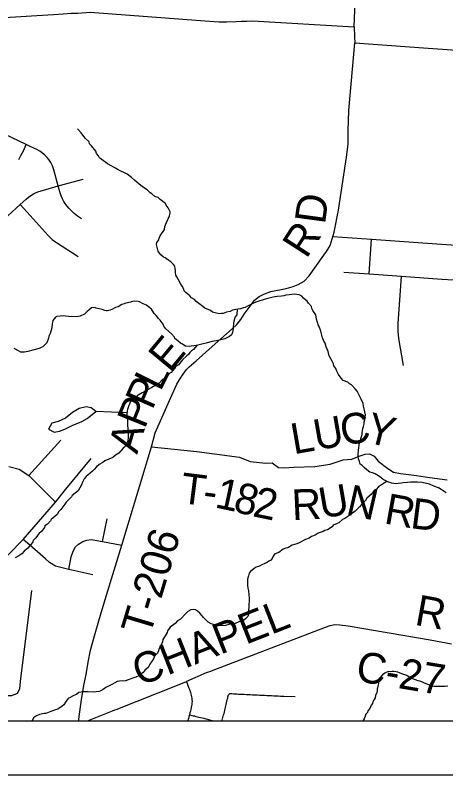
# Model space of a CAD drawing. Extents: x 0 to 34, y 0 to 22.
# Drawn here: x 3.374 to 4.173, y 14 to 15.409 of the extents above; entities that cross this region are included whole.
import ezdxf

# ---------------------------------------------------------------- set-up
doc = ezdxf.new("R2010")
doc.units = 0
for name, color, linetype in [('GM_X_Corporation', 7, 'Continuous'), ('GM_X_County_Road', 7, 'Continuous'), ('GM_X_County_Road_Text', 7, 'Continuous'), ('GM_X_Minor_Lake', 7, 'Continuous'), ('GM_X_Minor_River', 7, 'Continuous'), ('GM_X_Township_Road', 7, 'Continuous'), ('GM_X_Township_Road_Text', 7, 'Continuous'), ('SH_Data', 7, 'Continuous')]:
    doc.layers.add(name, color=color, linetype=linetype)

msp = doc.modelspace()

# ---------------------------------------------------------------- linework, layer by layer
at = {"layer": 'GM_X_Corporation'}
msp.add_lwpolyline([(2.9271, 14.1), (8.843, 14.1)], dxfattribs=at)
at = {"layer": 'GM_X_County_Road'}
msp.add_lwpolyline([(3.5081, 14.1), (3.5545, 14.1186), (3.559, 14.1205), (3.5612, 14.1214), (3.6782, 14.1678), (3.6919, 14.1734), (3.6922, 14.1735), (3.729, 14.1896), (3.7369, 14.1925), (3.7413, 14.1942), (3.9496, 14.2738), (3.9584, 14.277), (3.9672, 14.2787), (3.9763, 14.2784), (3.9918, 14.2761), (4.1437, 14.2504), (4.1833, 14.2432)], dxfattribs=at)
at = {"layer": 'GM_X_Minor_Lake'}
for points in [[(3.5235, 14.6739), (3.5152, 14.6809), (3.5057, 14.6826), (3.4928, 14.6794), (3.4801, 14.6724), (3.4674, 14.6616), (3.4539, 14.6557), (3.4417, 14.6525), (3.4358, 14.6412), (3.446, 14.6354), (3.4559, 14.6378), (3.4662, 14.6411), (3.4797, 14.6481)], [(3.4797, 14.6481), (3.4873, 14.6514), (3.4973, 14.6554), (3.5073, 14.6609), (3.5235, 14.6739)]]:
    msp.add_lwpolyline(points, dxfattribs=at)
at = {"layer": 'GM_X_Minor_River'}
for points in [[(3.6329, 15.0726), (3.6273, 15.078), (3.6243, 15.08), (3.6187, 15.0854), (3.6157, 15.0874), (3.6093, 15.0913), (3.604, 15.0959), (3.5999, 15.0994), (3.5954, 15.1029), (3.5898, 15.108), (3.5815, 15.1146), (3.5653, 15.1225), (3.56, 15.1252), (3.5454, 15.1338), (3.542, 15.1362), (3.5333, 15.142), (3.5303, 15.1448), (3.5285, 15.1482), (3.5251, 15.1528), (3.5237, 15.1567), (3.5155, 15.1667), (3.5121, 15.1709), (3.5111, 15.1744), (3.5043, 15.1802), (3.5013, 15.1841), (3.4961, 15.191), (3.4894, 15.1983)], [(3.9737, 14.7426), (3.97, 14.7499), (3.9686, 14.7537), (3.9652, 14.7587), (3.9645, 14.7625), (3.962, 14.7675), (3.9564, 14.7775), (3.9546, 14.7852), (3.9506, 14.794), (3.9492, 14.8005), (3.9466, 14.8047), (3.9441, 14.8108), (3.943, 14.8154), (3.9408, 14.823), (3.9376, 14.8315), (3.9361, 14.8349), (3.9346, 14.8391), (3.9328, 14.8452), (3.9315, 14.8533), (3.9263, 14.8613), (3.9244, 14.8652), (3.9237, 14.869), (3.9178, 14.8752), (3.9155, 14.879), (3.9088, 14.8845), (3.9058, 14.8883), (3.9005, 14.8903), (3.8964, 14.8911), (3.8918, 14.8916), (3.8869, 14.8913), (3.8823, 14.8902), (3.8758, 14.89), (3.8724, 14.8889), (3.8678, 14.8878), (3.8602, 14.8872), (3.8526, 14.8862), (3.84, 14.883), (3.8357, 14.8816), (3.8243, 14.8783), (3.8201, 14.8769), (3.8159, 14.8751), (3.8101, 14.8721), (3.8048, 14.8696), (3.8005, 14.867), (3.7975, 14.8663), (3.7917, 14.8645), (3.783, 14.8631), (3.7773, 14.8621), (3.773, 14.8598), (3.7662, 14.8581), (3.7631, 14.857), (3.7597, 14.8559), (3.7566, 14.8556), (3.7524, 14.8553), (3.7403, 14.8585), (3.7362, 14.8613), (3.726, 14.866), (3.7219, 14.8691), (3.7099, 14.8781), (3.7065, 14.8819), (3.7008, 14.8851), (3.6979, 14.8886), (3.6904, 14.8948), (3.6874, 14.8982), (3.6859, 14.9021), (3.6837, 14.9063), (3.6804, 14.9117), (3.6771, 14.9186), (3.6737, 14.924), (3.6719, 14.927), (3.6712, 14.932), (3.6713, 14.9354), (3.6706, 14.9388), (3.6699, 14.9434), (3.6677, 14.9469), (3.6624, 14.9515), (3.6591, 14.9543), (3.6549, 14.9574), (3.6519, 14.9593), (3.6489, 14.9605), (3.6444, 14.9648), (3.6414, 14.9675), (3.6392, 14.9713), (3.6381, 14.9767), (3.6364, 14.9839), (3.6368, 14.9877), (3.6403, 14.9926), (3.6411, 14.9956), (3.6431, 15.0002), (3.6509, 15.0118), (3.6517, 15.0171), (3.6545, 15.0247), (3.6601, 15.0368), (3.6613, 15.0417), (3.6613, 15.0447), (3.658, 15.0516), (3.6539, 15.0566), (3.6525, 15.0601), (3.6427, 15.0671), (3.6393, 15.071), (3.6329, 15.0726)], [(3.786, 14.8636), (3.7851, 14.8536), (3.782, 14.8498), (3.7796, 14.8419), (3.7791, 14.8388), (3.7786, 14.8289), (3.7778, 14.8236), (3.7769, 14.8206), (3.7753, 14.8165), (3.7715, 14.8131), (3.7627, 14.8087), (3.7577, 14.8076), (3.7474, 14.8052), (3.7386, 14.8042), (3.7283, 14.8009), (3.7226, 14.7995), (3.7104, 14.7967), (3.7005, 14.795), (3.6974, 14.7946), (3.6898, 14.7955), (3.6834, 14.7998), (3.6808, 14.801), (3.6756, 14.8053), (3.6703, 14.8092), (3.6692, 14.8119), (3.664, 14.8184), (3.6535, 14.8277), (3.6498, 14.8324), (3.6483, 14.8358), (3.6431, 14.8435), (3.6398, 14.8466), (3.6353, 14.8524), (3.6319, 14.8559), (3.6271, 14.8636), (3.6245, 14.8655), (3.6174, 14.8713), (3.6113, 14.8737), (3.6045, 14.8776), (3.6019, 14.8781), (3.5954, 14.8786), (3.5916, 14.8779), (3.5878, 14.8768), (3.579, 14.8751), (3.576, 14.874), (3.5718, 14.8725), (3.5648, 14.8685), (3.5599, 14.867), (3.5534, 14.863), (3.5499, 14.8619), (3.5453, 14.8608), (3.5427, 14.8609), (3.54, 14.8617), (3.5355, 14.8633), (3.5241, 14.8657), (3.5215, 14.8669), (3.5158, 14.8663), (3.5108, 14.8618), (3.5073, 14.8596), (3.5023, 14.8547), (3.4942, 14.8507), (3.4885, 14.8496), (3.4729, 14.8503), (3.4672, 14.8512), (3.4638, 14.8516), (3.4512, 14.8503), (3.4486, 14.8488), (3.4435, 14.8428), (3.4431, 14.839), (3.4427, 14.8364), (3.4418, 14.8292), (3.4389, 14.819), (3.4362, 14.8137), (3.4357, 14.8099), (3.4326, 14.8016), (3.4302, 14.7989), (3.4252, 14.7941), (3.4221, 14.7926), (3.4187, 14.7908), (3.4069, 14.7876), (3.3973, 14.7851), (3.3912, 14.7844), (3.3847, 14.7842), (3.3798, 14.7865), (3.3719, 14.7912)], [(3.7116, 14.797), (3.7046, 14.7888), (3.7011, 14.7866), (3.698, 14.7832), (3.6953, 14.7795), (3.6926, 14.7772), (3.6841, 14.7698), (3.6767, 14.7608), (3.6713, 14.7567), (3.6697, 14.7537), (3.6632, 14.7462), (3.6593, 14.7436), (3.6527, 14.7365), (3.647, 14.7331), (3.6408, 14.7264), (3.635, 14.7223), (3.6308, 14.7205), (3.6273, 14.7183), (3.6193, 14.7142), (3.6127, 14.7102), (3.6093, 14.7087), (3.6005, 14.7028), (3.5974, 14.6994), (3.5873, 14.6916), (3.5858, 14.6878), (3.5846, 14.6852), (3.5826, 14.678), (3.5817, 14.675), (3.5813, 14.6689), (3.5815, 14.6624), (3.5822, 14.6563), (3.5824, 14.6479), (3.5827, 14.6422), (3.583, 14.6384), (3.5833, 14.6293), (3.5836, 14.6259), (3.5831, 14.6194), (3.5815, 14.6164), (3.5772, 14.6085), (3.5745, 14.6063), (3.566, 14.5969), (3.5602, 14.5932), (3.5548, 14.5887), (3.5403, 14.5825), (3.5368, 14.5795), (3.5299, 14.5755), (3.5249, 14.5714), (3.5202, 14.5665), (3.5171, 14.5631), (3.509, 14.5557), (3.5059, 14.5535), (3.5021, 14.549), (3.4997, 14.5441), (3.4962, 14.5365), (3.4938, 14.5327), (3.491, 14.5267), (3.4795, 14.5182), (3.4783, 14.5155), (3.4729, 14.5099), (3.4683, 14.5058), (3.4663, 14.5024), (3.4589, 14.4923), (3.455, 14.4886), (3.4519, 14.4829), (3.4404, 14.4736), (3.4392, 14.471), (3.4341, 14.4653), (3.4291, 14.462), (3.4283, 14.459), (3.4225, 14.4515), (3.4186, 14.4481), (3.4124, 14.4395), (3.4074, 14.435), (3.4066, 14.4323), (3.4023, 14.426), (3.3996, 14.4233), (3.3976, 14.4203), (3.3903, 14.4148), (3.3861, 14.4099), (3.3807, 14.4062), (3.3738, 14.4025)], [(4.1734, 14.5231), (4.1696, 14.5254), (4.1644, 14.5293), (4.1595, 14.5324), (4.1508, 14.5356), (4.1425, 14.5392), (4.1292, 14.5421), (4.1201, 14.543), (4.1129, 14.5432), (4.1072, 14.5429), (4.1019, 14.5426), (4.0939, 14.5416), (4.0904, 14.5409), (4.0843, 14.5402), (4.0802, 14.5399), (4.0726, 14.5408), (4.0635, 14.544), (4.0601, 14.546), (4.0567, 14.5476), (4.05, 14.5534), (4.0417, 14.5581), (4.0368, 14.5605), (4.0319, 14.5617), (4.0266, 14.5656), (4.0214, 14.5702), (4.0176, 14.5737), (4.0142, 14.5765), (4.0128, 14.581), (4.0106, 14.5864), (4.0103, 14.5906), (4.0104, 14.5955), (4.0113, 14.6073), (4.0122, 14.6107), (4.0122, 14.6141), (4.015, 14.6198), (4.0154, 14.624), (4.0174, 14.6312), (4.0175, 14.635), (4.0191, 14.6422), (4.02, 14.646), (4.0212, 14.6509), (4.0216, 14.6547), (4.0229, 14.6592), (4.0238, 14.6676), (4.0213, 14.679), (4.0202, 14.684), (4.0196, 14.6886), (4.0159, 14.697), (4.0107, 14.7066), (4.0082, 14.712), (4.0048, 14.7158), (3.9981, 14.7232), (3.9939, 14.7251), (3.991, 14.7286), (3.9826, 14.7318), (3.9785, 14.7357), (3.9737, 14.7426)], [(3.5815, 14.6718), (3.5235, 14.6739)], [(4.0635, 14.544), (4.0554, 14.5392), (4.0477, 14.534), (4.0439, 14.5295), (4.0381, 14.5251), (4.0342, 14.5202), (4.0265, 14.5135), (4.0237, 14.5086), (4.0168, 14.5019), (4.0125, 14.497), (4.0048, 14.4891), (3.9929, 14.4802), (3.9856, 14.4758), (3.9813, 14.4736), (3.9744, 14.4676), (3.9713, 14.4662), (3.964, 14.4629), (3.9621, 14.4599), (3.9536, 14.4547), (3.9487, 14.4532), (3.9456, 14.4514), (3.9361, 14.4481), (3.9303, 14.4448), (3.9238, 14.4423), (3.9192, 14.4393), (3.9123, 14.4368), (3.9008, 14.4301), (3.8962, 14.4287), (3.8878, 14.4262), (3.8797, 14.4214), (3.8763, 14.4203), (3.8709, 14.4185), (3.8628, 14.4125), (3.8594, 14.4115), (3.8552, 14.4092), (3.8528, 14.4055), (3.8509, 14.401), (3.8481, 14.398), (3.8447, 14.3961), (3.8412, 14.3939), (3.8374, 14.3921), (3.8313, 14.3895), (3.8271, 14.3873), (3.8209, 14.3851), (3.8171, 14.3829), (3.8105, 14.3773), (3.8082, 14.3743), (3.8066, 14.3694), (3.805, 14.363), (3.8052, 14.3557), (3.8052, 14.3519), (3.8058, 14.3462), (3.8069, 14.3413), (3.8075, 14.3336), (3.8078, 14.3275), (3.8075, 14.3104), (3.8071, 14.3063), (3.8066, 14.3006), (3.8065, 14.2971), (3.8053, 14.2934), (3.8011, 14.2896), (3.798, 14.287), (3.7888, 14.2838), (3.7823, 14.2805), (3.7777, 14.2798), (3.7705, 14.2788), (3.764, 14.277), (3.7511, 14.2764), (3.7416, 14.2789), (3.7374, 14.2801), (3.7322, 14.2829), (3.7262, 14.2887), (3.7236, 14.2921), (3.721, 14.2952), (3.7165, 14.2999), (3.7124, 14.3037), (3.7082, 14.3061), (3.7044, 14.3065), (3.6995, 14.3059), (3.6945, 14.3029), (3.6914, 14.2999), (3.6809, 14.2887), (3.6752, 14.2854), (3.6705, 14.2805), (3.6613, 14.2738), (3.6566, 14.2674), (3.6558, 14.264), (3.6523, 14.258), (3.648, 14.2512), (3.6471, 14.2467), (3.6444, 14.2399), (3.6405, 14.2331), (3.64, 14.2301), (3.6377, 14.2259), (3.6323, 14.2199), (3.6314, 14.2165), (3.6283, 14.2113), (3.6236, 14.2053), (3.6205, 14.1992)], [(3.6205, 14.1992), (3.6151, 14.1948), (3.6116, 14.1899), (3.607, 14.1869), (3.6031, 14.1839), (3.5978, 14.1814), (3.5932, 14.1799), (3.5901, 14.1789), (3.5836, 14.1759), (3.5783, 14.1745), (3.5672, 14.1735), (3.563, 14.1729), (3.5546, 14.1684), (3.5496, 14.1659), (3.5419, 14.1622), (3.5373, 14.1585), (3.5327, 14.1555), (3.5296, 14.1544), (3.5239, 14.1538), (3.5205, 14.1534), (3.5095, 14.154), (3.5, 14.1542), (3.492, 14.1528), (3.4881, 14.1498), (3.4801, 14.1462), (3.4759, 14.1436), (3.4728, 14.1421), (3.4697, 14.1387), (3.467, 14.135), (3.4642, 14.1301), (3.4611, 14.1271), (3.4531, 14.1219), (3.4485, 14.1205), (3.4401, 14.1176), (3.4305, 14.1139), (3.4274, 14.1136), (3.4191, 14.1119), (3.4137, 14.1093), (3.4079, 14.1056), (3.4054, 14.1)], [(4.1769, 14.1644), (4.1712, 14.1637), (4.1647, 14.1638), (4.1552, 14.1636), (4.1514, 14.1637), (4.1461, 14.1649), (4.1427, 14.1661), (4.1385, 14.1684), (4.1336, 14.1701), (4.1283, 14.1724), (4.1246, 14.1736), (4.1215, 14.1745), (4.1166, 14.1764), (4.1117, 14.1781), (4.1049, 14.1812), (4.1004, 14.1843), (4.091, 14.1875), (4.0872, 14.1891), (4.0838, 14.1907), (4.0766, 14.1916), (4.0732, 14.1917), (4.0694, 14.1913), (4.0659, 14.1914), (4.0598, 14.1885), (4.0552, 14.1855), (4.0513, 14.1803), (4.0481, 14.1727), (4.0481, 14.1693), (4.0465, 14.1647), (4.0456, 14.1591), (4.0452, 14.1556), (4.0447, 14.1526), (4.0424, 14.1469), (4.0419, 14.1428), (4.04, 14.1398), (4.0372, 14.1356), (4.0368, 14.1326), (4.0345, 14.1292), (4.0321, 14.1228), (4.0282, 14.1187), (4.0278, 14.1156), (4.0247, 14.1126), (4.0235, 14.1089), (4.0215, 14.1036), (4.0192, 14.1)]]:
    msp.add_lwpolyline(points, dxfattribs=at)
at = {"layer": 'GM_X_Township_Road'}
for p, q in [((3.3832, 15.0579), (3.4015, 15.0377)), ((4.0304, 14.9292), (4.0349, 14.9935)), ((4.1475, 14.9855), (4.1918, 14.9824)), ((4.0896, 14.9073), (4.0909, 14.9249)), ((4.1655, 14.9197), (4.1872, 14.9182)), ((3.3993, 14.5553), (3.4587, 14.621)), ((3.5359, 14.4327), (3.5443, 14.475))]:
    msp.add_line(p, q, dxfattribs=at)
for points in [[(4.0031, 15.3877), (4.0065, 15.4807), (4.009, 15.4886), (4.0121, 15.4927), (4.016, 15.4952), (4.0217, 15.4962), (4.0558, 15.4965), (4.0626, 15.4967), (4.0657, 15.4985), (4.0684, 15.5037), (4.0706, 15.5124), (4.0714, 15.5283), (4.0764, 15.65), (4.0776, 15.6825)], [(2.8777, 15.4194), (3.0526, 15.4004), (3.0789, 15.3973), (3.0941, 15.3956), (3.122, 15.3935), (3.1613, 15.3944), (3.2012, 15.3971), (3.2627, 15.4013), (3.3345, 15.404), (3.4142, 15.4085), (3.4451, 15.4103), (3.4629, 15.4118), (3.4785, 15.4129), (3.4903, 15.4133), (3.5128, 15.4146), (3.7177, 15.3992), (3.7519, 15.397), (3.766, 15.397), (3.784, 15.3976), (3.7936, 15.3981), (3.804, 15.3981), (3.814, 15.3987), (4.0031, 15.3877)], [(4.0031, 15.3877), (4.0033, 15.3692), (4.0038, 15.3577)], [(3.6269, 14.6084), (3.6339, 14.6342), (3.6653, 14.7055), (3.6738, 14.725), (3.6793, 14.734), (3.6856, 14.7433), (3.6915, 14.7519), (3.6966, 14.7567), (3.7094, 14.7681), (3.7447, 14.7995), (3.7765, 14.8271), (3.7854, 14.8356), (3.7925, 14.8445), (3.7988, 14.8546), (3.8133, 14.8747), (3.818, 14.8803), (3.8265, 14.8873), (3.835, 14.8916), (3.8484, 14.8966), (3.8769, 14.9023), (3.8895, 14.9058), (3.8987, 14.9097), (3.9101, 14.9158), (3.9195, 14.9258), (3.9467, 14.9643), (3.9515, 14.971), (3.9585, 14.9818), (3.966, 15.0069), (3.9735, 15.0475), (3.9886, 15.146), (3.9914, 15.1697), (3.9918, 15.1948), (3.9932, 15.2327), (4.0038, 15.3577)], [(4.0038, 15.3577), (4.1317, 15.3488), (4.4737, 15.3246)], [(3.4972, 15.0313), (3.4896, 15.0367), (3.4832, 15.0416), (3.4789, 15.0454), (3.4734, 15.051), (3.4682, 15.0578), (3.4645, 15.0634), (3.4619, 15.0686), (3.4594, 15.0742), (3.457, 15.0818), (3.4535, 15.0925), (3.4454, 15.1226), (3.4429, 15.1298), (3.44, 15.1358), (3.4365, 15.1414), (3.4334, 15.1454), (3.4292, 15.1495), (3.4254, 15.1525), (3.4194, 15.1571), (3.4126, 15.1609), (3.4029, 15.1652), (3.3942, 15.1691), (3.3543, 15.1885)], [(3.3805, 15.1418), (3.3847, 15.1488), (3.3895, 15.1576), (3.3942, 15.1691)], [(3.3142, 14.9952), (3.3369, 15.0158), (3.3832, 15.0579), (3.3944, 15.068), (3.3987, 15.0716), (3.4032, 15.0749), (3.408, 15.0777), (3.413, 15.0802), (3.4181, 15.0824), (3.4244, 15.0838), (3.4535, 15.0925), (3.5002, 15.1049)], [(3.4015, 15.0377), (3.4354, 15.0004), (3.4389, 14.9967), (3.4427, 14.9934), (3.4466, 14.9902), (3.4508, 14.9873), (3.4907, 14.9614)], [(3.9635, 14.9985), (4.0349, 14.9935), (4.1475, 14.9855)], [(3.9835, 14.9325), (4.0304, 14.9292), (4.0909, 14.9249), (4.1655, 14.9197)], [(4.0943, 14.7592), (4.086, 14.8096), (4.0851, 14.8164), (4.0845, 14.8233), (4.0844, 14.8302), (4.0847, 14.8371), (4.0896, 14.9073)], [(3.4922, 14.1033), (3.4971, 14.1398), (3.5021, 14.1687), (3.5059, 14.1858), (3.5093, 14.2091), (3.5135, 14.231), (3.5226, 14.2623), (3.5335, 14.3003), (3.5435, 14.3331), (3.5716, 14.4258), (3.6269, 14.6084)], [(3.6269, 14.6084), (3.7108, 14.5997), (3.7902, 14.5896), (3.8099, 14.5813), (3.839, 14.5781), (3.8508, 14.5788), (3.8627, 14.5701), (3.8745, 14.5694), (3.8907, 14.571), (3.9301, 14.5719), (3.958, 14.5765), (3.9826, 14.5845), (3.9983, 14.5858), (4.0124, 14.591), (4.0234, 14.5949), (4.0315, 14.5956), (4.0397, 14.591), (4.0476, 14.5817), (4.0655, 14.5683), (4.0757, 14.5615), (4.0886, 14.5587), (4.1183, 14.5553), (4.1428, 14.5514), (4.1752, 14.5473)], [(3.0882, 14.3014), (3.1127, 14.297), (3.1578, 14.3002), (3.2001, 14.3097), (3.2293, 14.3188), (3.2475, 14.3271), (3.2768, 14.3417), (3.3092, 14.361), (3.3333, 14.3804), (3.3887, 14.4366), (3.4171, 14.4693), (3.4487, 14.5057), (3.4681, 14.5298), (3.5146, 14.5871)], [(3.362, 14.5718), (3.3814, 14.5669), (3.3993, 14.5553), (3.4487, 14.5057)], [(3.5179, 14.3712), (3.4732, 14.3811), (3.4485, 14.3868), (3.4375, 14.3938), (3.43, 14.4008), (3.4204, 14.4094), (3.4011, 14.4263), (3.3887, 14.4366)], [(3.4732, 14.3811), (3.4775, 14.4047), (3.4815, 14.4152), (3.4858, 14.4229), (3.4916, 14.4282), (3.4992, 14.433), (3.5067, 14.4355), (3.5152, 14.4363), (3.5359, 14.4327), (3.5716, 14.4258)], [(3.2386, 14.1545), (3.2958, 14.1513), (3.3144, 14.1484), (3.3545, 14.147), (3.3677, 14.147), (3.3783, 14.1513), (3.3823, 14.1596), (3.3837, 14.1731), (3.4046, 14.3419)], [(3.6919, 14.1734), (3.6939, 14.1674), (3.6964, 14.161), (3.6977, 14.1573), (3.6993, 14.1527), (3.7, 14.1501), (3.7007, 14.1476), (3.7012, 14.1447), (3.7017, 14.1419), (3.7019, 14.139), (3.702, 14.1361), (3.7019, 14.1333), (3.7016, 14.1305), (3.7012, 14.1278), (3.7006, 14.1249), (3.6998, 14.1216), (3.699, 14.1182), (3.6981, 14.1148), (3.6973, 14.1115), (3.6942, 14.1)], [(3.7579, 14.1), (3.7582, 14.1013), (3.7588, 14.1036), (3.7594, 14.1061), (3.7601, 14.1086), (3.7607, 14.1113), (3.7614, 14.114), (3.762, 14.1167), (3.7626, 14.1194), (3.7633, 14.1222), (3.7639, 14.125), (3.7646, 14.1278), (3.7653, 14.1307), (3.766, 14.1336), (3.7668, 14.1365), (3.7675, 14.1395), (3.7682, 14.1422), (3.7687, 14.1444), (3.7691, 14.1464), (3.7697, 14.1483), (3.7707, 14.1498), (3.7721, 14.1506), (3.7737, 14.1507), (3.7759, 14.1506), (3.7787, 14.1503), (3.7817, 14.1502), (3.7849, 14.15), (3.7882, 14.1498), (3.7917, 14.1496), (3.7953, 14.1495), (3.799, 14.1493), (3.8028, 14.1491), (3.8067, 14.1489), (3.8106, 14.1487), (3.8145, 14.1485), (3.8186, 14.1483), (3.8228, 14.1482), (3.8271, 14.148), (3.8316, 14.1478), (3.8362, 14.1476), (3.8407, 14.1474), (3.8451, 14.1472), (3.8495, 14.147), (3.8537, 14.1468), (3.858, 14.1465), (3.8621, 14.1463), (3.8661, 14.1461), (3.8702, 14.1459), (3.8725, 14.1458), (3.8934, 14.1453)], [(3.6973, 14.1115), (3.6986, 14.1111), (3.6997, 14.1108), (3.7016, 14.1103), (3.704, 14.1097), (3.7065, 14.1092), (3.7092, 14.1084), (3.712, 14.1077), (3.7149, 14.107), (3.7179, 14.1063), (3.721, 14.1054), (3.7242, 14.1048), (3.7276, 14.1039), (3.7309, 14.103), (3.7343, 14.1021), (3.7376, 14.1014), (3.7425, 14.1), (3.7425, 14.1)], [(3.4917, 14.1), (3.4921, 14.1023), (3.4922, 14.1033)]]:
    msp.add_lwpolyline(points, dxfattribs=at)
at = {"layer": 'SH_Data'}
for p, q in [((2.1, 14.1), (8.9, 14.1)), ((2, 14), (9, 14))]:
    msp.add_line(p, q, dxfattribs=at)

# ---------------------------------------------------------------- texts
at = {"layer": 'GM_X_County_Road_Text'}
for s, height, rotation, p in [('R', 0.0568, 349.8344, (4.1134, 14.2786)), ('CHAPEL', 0.05682, 21.4425, (3.6051, 14.1639)), ('C-27', 0.05682, 350.5421, (4.0039, 14.1743))]:
    msp.add_text(s, height=height, rotation=rotation, dxfattribs=at).set_placement(p)
at = {"layer": 'GM_X_Township_Road_Text'}
for s, height, rotation, p in [('D', 0.0568, 82.2449, (3.9486, 15.02)), ('R', 0.0568, 57.1771, (3.9142, 14.9559)), ('E', 0.0568, 50.3261, (3.6605, 14.7449)), ('L', 0.0568, 63.3104, (3.6433, 14.7097)), ('P', 0.0568, 66.2218, (3.6282, 14.6753)), ('P', 0.0568, 68.1298, (3.6141, 14.6402)), ('C', 0.0568, 9.3263, (3.9816, 14.6104)), ('Y', 0.0568, 345.7376, (4.0215, 14.6182)), ('U', 0.0568, 9.8774, (3.9325, 14.6018)), ('L', 0.0568, 9.8843, (3.8906, 14.5945)), ('A', 0.0568, 73.307, (3.6002, 14.5936)), ('T', 0.0568, 352.85, (3.6785, 14.5046)), ('1', 0.0568, 347.9899, (3.7425, 14.4964)), ('8', 0.0568, 345.7353, (3.7762, 14.4893)), ('2', 0.0568, 348.2392, (3.8127, 14.48)), ('R', 0.0568, 2.6353, (3.8882, 14.4724)), ('U', 0.0568, 9.7644, (3.9423, 14.4753)), ('N', 0.0568, 347.0603, (3.9857, 14.484)), ('-', 0.0568, 352.4848, (3.7205, 14.4993)), ('R', 0.0568, 349.8045, (4.0566, 14.4667)), ('D', 0.0568, 352.7723, (4.1056, 14.4579)), ('T-206', 0.05682, 73.2221, (3.6239, 14.2558))]:
    msp.add_text(s, height=height, rotation=rotation, dxfattribs=at).set_placement(p)

doc.saveas('drawing.dxf')
